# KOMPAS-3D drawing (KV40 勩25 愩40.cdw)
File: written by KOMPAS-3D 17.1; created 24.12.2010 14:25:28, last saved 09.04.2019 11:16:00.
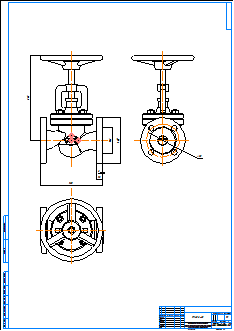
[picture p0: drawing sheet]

Title block, sheet 1: name: KV 40 Ду25; material: Внимание! Данный продукт является объектом авторского права ООО «Торговый Дом АДЛ». / Запрещается изменение, копирование, распространение / (в том числе путем копирования на другие сайты и ресурсы в Интернете) / или любое иное использование информации и объектов без предварительного / согласия правообладателя (ООО «Торговый Дом АДЛ»).; scale: 1:1; sheets: 1; organisation: ООО "Торговый дом АДЛ"; sheet format: A1; stored path: \\adlc.lan\data\АДЛ_ПКД\3D-модели\ADL production\Вентили ГРАНВЕНТ\KV40\KOMPAS 2D\KV 40 Ду25.cdw

Views: Спереди 1, Проекционный вид 2, Вид 5
Dimensions and other numbers on the sheet: 68; 115; 220; 85; 2; 18; 160; 1:1; 1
